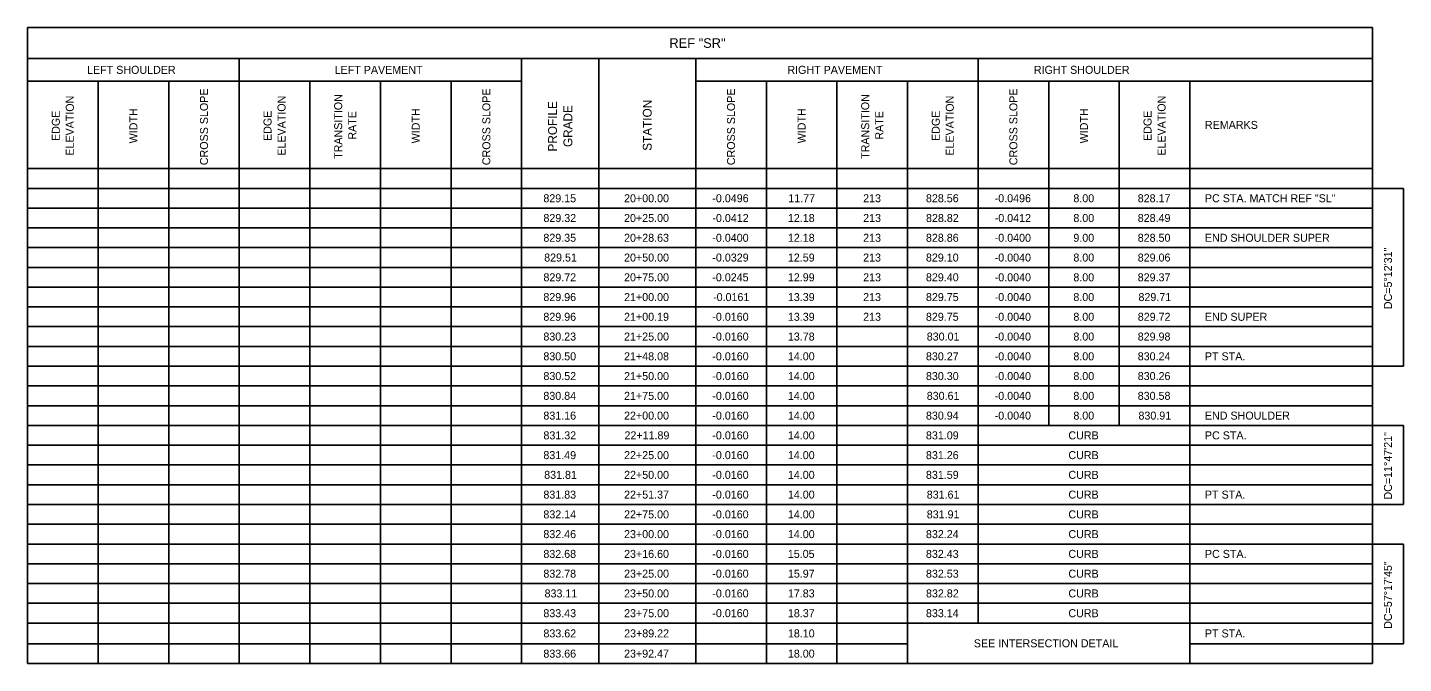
# Model space of a CAD drawing. Extents: x -31.2 to 34, y 0 to 30.3.
# Drawn here: x -31.16 to -7.08, y 4.37 to 15.51 of the extents above; entities that cross this region are included whole.
import ezdxf

# ---------------------------------------------------------------- set-up
doc = ezdxf.new("R2010")
doc.units = 0
doc.layers.add('Default', color=7, linetype='Continuous')

msp = doc.modelspace()

# ---------------------------------------------------------------- linework, layer by layer
at = {"layer": 'Default'}
for p, q in [((-31.159, 15.508), (-7.624, 15.508)), ((-31.159, 15.508), (-31.159, 4.374)), ((-7.624, 15.508), (-7.624, 4.374)), ((-31.159, 14.965), (-7.624, 14.965)), ((-27.454, 14.965), (-27.454, 4.374)), ((-22.513, 14.965), (-22.513, 4.374)), ((-21.162, 14.965), (-21.162, 4.374)), ((-19.466, 14.965), (-19.466, 4.374)), ((-14.525, 14.965), (-14.525, 5.083)), ((-31.159, 14.569), (-22.513, 14.569)), ((-29.924, 14.569), (-29.924, 13.038)), ((-28.689, 14.569), (-28.689, 13.038)), ((-26.218, 14.569), (-26.218, 4.374)), ((-24.983, 14.569), (-24.983, 4.374)), ((-23.748, 14.569), (-23.748, 4.374)), ((-19.466, 14.569), (-7.624, 14.569)), ((-18.23, 14.569), (-18.23, 4.374)), ((-16.995, 14.569), (-16.995, 4.374)), ((-15.76, 14.569), (-15.76, 4.374)), ((-13.289, 14.569), (-13.289, 13.038)), ((-12.054, 14.569), (-12.054, 13.038)), ((-10.819, 14.569), (-10.819, 4.374)), ((-31.159, 13.038), (-7.624, 13.038)), ((-29.924, 13.038), (-29.924, 4.374)), ((-28.689, 13.038), (-28.689, 4.374)), ((-13.289, 13.038), (-13.289, 8.541)), ((-12.054, 13.038), (-12.054, 8.541)), ((-31.159, 12.692), (-7.624, 12.692)), ((-7.624, 12.692), (-7.08, 12.692)), ((-7.08, 12.692), (-7.08, 9.579)), ((-31.159, 12.346), (-7.624, 12.346)), ((-31.159, 12), (-7.624, 12)), ((-31.159, 11.654), (-7.624, 11.654)), ((-31.159, 11.308), (-7.624, 11.308)), ((-31.159, 10.962), (-7.624, 10.962)), ((-31.159, 10.616), (-7.624, 10.616)), ((-31.159, 10.271), (-7.624, 10.271)), ((-31.159, 9.925), (-7.624, 9.925)), ((-31.159, 9.579), (-7.624, 9.579)), ((-7.624, 9.579), (-7.08, 9.579)), ((-31.159, 9.233), (-7.624, 9.233)), ((-31.159, 8.887), (-7.624, 8.887)), ((-31.159, 8.541), (-7.624, 8.541)), ((-7.624, 8.541), (-7.08, 8.541)), ((-7.08, 8.541), (-7.08, 7.158)), ((-31.159, 8.195), (-7.624, 8.195)), ((-31.159, 7.85), (-7.624, 7.85)), ((-31.159, 7.504), (-7.624, 7.504)), ((-31.159, 7.158), (-7.624, 7.158)), ((-7.624, 7.158), (-7.08, 7.158)), ((-31.159, 6.812), (-7.624, 6.812)), ((-31.159, 6.466), (-7.624, 6.466)), ((-7.624, 6.466), (-7.08, 6.466)), ((-7.08, 6.466), (-7.08, 4.72)), ((-31.159, 6.12), (-7.624, 6.12)), ((-31.159, 5.774), (-7.624, 5.774)), ((-31.159, 5.428), (-7.624, 5.428)), ((-31.159, 5.083), (-7.624, 5.083)), ((-31.159, 4.72), (-15.76, 4.72)), ((-10.819, 4.72), (-7.624, 4.72)), ((-7.624, 4.72), (-7.08, 4.72)), ((-31.159, 4.374), (-7.624, 4.374))]:
    msp.add_line(p, q, dxfattribs=at)

# ---------------------------------------------------------------- texts
for s, height, p in [('REF "SR"', 0.168, (-19.927, 15.152)), ('LEFT SHOULDER', 0.14, (-30.117, 14.697)), ('LEFT PAVEMENT', 0.14, (-25.785, 14.697)), ('RIGHT PAVEMENT', 0.14, (-17.862, 14.697)), ('RIGHT SHOULDER', 0.14, (-13.548, 14.697)), ('REMARKS', 0.14, (-10.555, 13.733)), ('829.15', 0.14, (-22.132, 12.449)), ('20+00.00', 0.14, (-20.72, 12.449)), ('-0.0496', 0.14, (-19.175, 12.449)), ('11.77', 0.14, (-17.846, 12.449)), ('213', 0.14, (-16.536, 12.449)), ('828.56', 0.14, (-15.437, 12.449)), ('-0.0496', 0.14, (-14.234, 12.449)), ('8.00', 0.14, (-12.857, 12.449)), ('828.17', 0.14, (-11.731, 12.449)), ('PC STA. MATCH REF "SL"', 0.14, (-10.555, 12.449)), ('829.32', 0.14, (-22.131, 12.103)), ('20+25.00', 0.14, (-20.72, 12.103)), ('-0.0412', 0.14, (-19.174, 12.103)), ('12.18', 0.14, (-17.853, 12.103)), ('213', 0.14, (-16.536, 12.103)), ('828.82', 0.14, (-15.436, 12.103)), ('-0.0412', 0.14, (-14.233, 12.103)), ('8.00', 0.14, (-12.857, 12.103)), ('828.49', 0.14, (-11.731, 12.103)), ('829.35', 0.14, (-22.132, 11.757)), ('20+28.63', 0.14, (-20.72, 11.757)), ('-0.0400', 0.14, (-19.175, 11.757)), ('12.18', 0.14, (-17.853, 11.757)), ('213', 0.14, (-16.536, 11.757)), ('828.86', 0.14, (-15.437, 11.757)), ('-0.0400', 0.14, (-14.234, 11.757)), ('9.00', 0.14, (-12.857, 11.757)), ('828.50', 0.14, (-11.731, 11.757)), ('END SHOULDER SUPER', 0.14, (-10.555, 11.757)), ('829.51', 0.14, (-22.118, 11.411)), ('20+50.00', 0.14, (-20.72, 11.411)), ('-0.0329', 0.14, (-19.175, 11.411)), ('12.59', 0.14, (-17.853, 11.411)), ('213', 0.14, (-16.536, 11.411)), ('829.10', 0.14, (-15.437, 11.411)), ('-0.0040', 0.14, (-14.234, 11.411)), ('8.00', 0.14, (-12.857, 11.411)), ('829.06', 0.14, (-11.731, 11.411)), ('829.72', 0.14, (-22.131, 11.065)), ('20+75.00', 0.14, (-20.72, 11.065)), ('-0.0245', 0.14, (-19.176, 11.065)), ('12.99', 0.14, (-17.853, 11.065)), ('213', 0.14, (-16.536, 11.065)), ('829.40', 0.14, (-15.437, 11.065)), ('-0.0040', 0.14, (-14.234, 11.065)), ('8.00', 0.14, (-12.857, 11.065)), ('829.37', 0.14, (-11.731, 11.065)), ('829.96', 0.14, (-22.132, 10.719)), ('21+00.00', 0.14, (-20.72, 10.719)), ('-0.0161', 0.14, (-19.162, 10.719)), ('13.39', 0.14, (-17.853, 10.719)), ('213', 0.14, (-16.536, 10.719)), ('829.75', 0.14, (-15.437, 10.719)), ('-0.0040', 0.14, (-14.234, 10.719)), ('8.00', 0.14, (-12.857, 10.719)), ('829.71', 0.14, (-11.718, 10.719)), ('829.96', 0.14, (-22.132, 10.374)), ('21+00.19', 0.14, (-20.72, 10.374)), ('-0.0160', 0.14, (-19.175, 10.374)), ('13.39', 0.14, (-17.853, 10.374)), ('213', 0.14, (-16.536, 10.374)), ('829.75', 0.14, (-15.437, 10.374)), ('-0.0040', 0.14, (-14.234, 10.374)), ('8.00', 0.14, (-12.857, 10.374)), ('829.72', 0.14, (-11.73, 10.374)), ('END SUPER', 0.14, (-10.555, 10.374)), ('830.23', 0.14, (-22.132, 10.028)), ('21+25.00', 0.14, (-20.72, 10.028)), ('-0.0160', 0.14, (-19.175, 10.028)), ('13.78', 0.14, (-17.853, 10.028)), ('830.01', 0.14, (-15.423, 10.028)), ('-0.0040', 0.14, (-14.234, 10.028)), ('8.00', 0.14, (-12.857, 10.028)), ('829.98', 0.14, (-11.731, 10.028)), ('830.50', 0.14, (-22.132, 9.682)), ('21+48.08', 0.14, (-20.72, 9.682)), ('-0.0160', 0.14, (-19.175, 9.682)), ('14.00', 0.14, (-17.853, 9.682)), ('830.27', 0.14, (-15.437, 9.682)), ('-0.0040', 0.14, (-14.234, 9.682)), ('8.00', 0.14, (-12.857, 9.682)), ('830.24', 0.14, (-11.731, 9.682)), ('PT STA.', 0.14, (-10.555, 9.682)), ('830.52', 0.14, (-22.131, 9.336)), ('21+50.00', 0.14, (-20.72, 9.336)), ('-0.0160', 0.14, (-19.175, 9.336)), ('14.00', 0.14, (-17.853, 9.336)), ('830.30', 0.14, (-15.437, 9.336)), ('-0.0040', 0.14, (-14.234, 9.336)), ('8.00', 0.14, (-12.857, 9.336)), ('830.26', 0.14, (-11.731, 9.336)), ('830.84', 0.14, (-22.132, 8.99)), ('21+75.00', 0.14, (-20.72, 8.99)), ('-0.0160', 0.14, (-19.175, 8.99)), ('14.00', 0.14, (-17.853, 8.99)), ('830.61', 0.14, (-15.423, 8.99)), ('-0.0040', 0.14, (-14.234, 8.99)), ('8.00', 0.14, (-12.857, 8.99)), ('830.58', 0.14, (-11.731, 8.99)), ('831.16', 0.14, (-22.132, 8.644)), ('22+00.00', 0.14, (-20.72, 8.644)), ('-0.0160', 0.14, (-19.175, 8.644)), ('14.00', 0.14, (-17.853, 8.644)), ('830.94', 0.14, (-15.437, 8.644)), ('-0.0040', 0.14, (-14.234, 8.644)), ('8.00', 0.14, (-12.857, 8.644)), ('830.91', 0.14, (-11.718, 8.644)), ('END SHOULDER', 0.14, (-10.555, 8.644)), ('831.32', 0.14, (-22.131, 8.298)), ('22+11.89', 0.14, (-20.713, 8.298)), ('-0.0160', 0.14, (-19.175, 8.298)), ('14.00', 0.14, (-17.853, 8.298)), ('831.09', 0.14, (-15.437, 8.298)), ('CURB', 0.14, (-12.944, 8.298)), ('PC STA.', 0.14, (-10.555, 8.298)), ('831.49', 0.14, (-22.132, 7.952)), ('22+25.00', 0.14, (-20.72, 7.952)), ('-0.0160', 0.14, (-19.175, 7.952)), ('14.00', 0.14, (-17.853, 7.952)), ('831.26', 0.14, (-15.437, 7.952)), ('CURB', 0.14, (-12.944, 7.952)), ('831.81', 0.14, (-22.118, 7.607)), ('22+50.00', 0.14, (-20.72, 7.607)), ('-0.0160', 0.14, (-19.175, 7.607)), ('14.00', 0.14, (-17.853, 7.607)), ('831.59', 0.14, (-15.437, 7.607)), ('CURB', 0.14, (-12.944, 7.607)), ('831.83', 0.14, (-22.132, 7.261)), ('22+51.37', 0.14, (-20.72, 7.261)), ('-0.0160', 0.14, (-19.175, 7.261)), ('14.00', 0.14, (-17.853, 7.261)), ('831.61', 0.14, (-15.423, 7.261)), ('CURB', 0.14, (-12.944, 7.261)), ('PT STA.', 0.14, (-10.555, 7.261)), ('832.14', 0.14, (-22.132, 6.915)), ('22+75.00', 0.14, (-20.72, 6.915)), ('-0.0160', 0.14, (-19.175, 6.915)), ('14.00', 0.14, (-17.853, 6.915)), ('831.91', 0.14, (-15.423, 6.915)), ('CURB', 0.14, (-12.944, 6.915)), ('832.46', 0.14, (-22.132, 6.569)), ('23+00.00', 0.14, (-20.72, 6.569)), ('-0.0160', 0.14, (-19.175, 6.569)), ('14.00', 0.14, (-17.853, 6.569)), ('832.24', 0.14, (-15.437, 6.569)), ('CURB', 0.14, (-12.944, 6.569)), ('832.68', 0.14, (-22.132, 6.223)), ('23+16.60', 0.14, (-20.72, 6.223)), ('-0.0160', 0.14, (-19.175, 6.223)), ('15.05', 0.14, (-17.854, 6.223)), ('832.43', 0.14, (-15.437, 6.223)), ('CURB', 0.14, (-12.944, 6.223)), ('PC STA.', 0.14, (-10.555, 6.223)), ('832.78', 0.14, (-22.132, 5.877)), ('23+25.00', 0.14, (-20.72, 5.877)), ('-0.0160', 0.14, (-19.175, 5.877)), ('15.97', 0.14, (-17.853, 5.877)), ('832.53', 0.14, (-15.437, 5.877)), ('CURB', 0.14, (-12.944, 5.877)), ('833.11', 0.14, (-22.111, 5.531)), ('23+50.00', 0.14, (-20.72, 5.531)), ('-0.0160', 0.14, (-19.175, 5.531)), ('17.83', 0.14, (-17.853, 5.531)), ('832.82', 0.14, (-15.436, 5.531)), ('CURB', 0.14, (-12.944, 5.531)), ('833.43', 0.14, (-22.132, 5.185)), ('23+75.00', 0.14, (-20.72, 5.185)), ('-0.0160', 0.14, (-19.175, 5.185)), ('18.37', 0.14, (-17.853, 5.185)), ('833.14', 0.14, (-15.437, 5.185)), ('CURB', 0.14, (-12.944, 5.185)), ('833.62', 0.14, (-22.131, 4.831)), ('23+89.22', 0.14, (-20.719, 4.831)), ('18.10', 0.14, (-17.853, 4.831)), ('PT STA.', 0.14, (-10.555, 4.831)), ('833.66', 0.14, (-22.132, 4.477)), ('23+92.47', 0.14, (-20.72, 4.477)), ('18.00', 0.14, (-17.853, 4.477)), ('SEE INTERSECTION DETAIL', 0.14, (-14.599, 4.658))]:
    msp.add_text(s, height=height, dxfattribs=at).set_placement(p)
for s, height, p in [('ELEVATION', 0.14, (-30.349, 13.264)), ('CROSS SLOPE', 0.14, (-28.001, 13.098)), ('ELEVATION', 0.14, (-26.644, 13.264)), ('TRANSITION ', 0.14, (-25.653, 13.208)), ('CROSS SLOPE', 0.14, (-23.06, 13.098)), ('PROFILE ', 0.154, (-21.895, 13.338)), ('STATION', 0.154, (-20.237, 13.35)), ('CROSS SLOPE', 0.14, (-18.778, 13.098)), ('TRANSITION ', 0.14, (-16.43, 13.208)), ('ELEVATION', 0.14, (-14.95, 13.264)), ('CROSS SLOPE', 0.14, (-13.837, 13.098)), ('ELEVATION', 0.14, (-11.244, 13.264)), ('EDGE ', 0.14, (-30.594, 13.522)), ('WIDTH', 0.14, (-29.237, 13.48)), ('EDGE ', 0.14, (-26.889, 13.522)), ('RATE', 0.14, (-25.408, 13.545)), ('WIDTH', 0.14, (-24.296, 13.48)), ('GRADE', 0.154, (-21.626, 13.416)), ('WIDTH', 0.14, (-17.543, 13.48)), ('RATE', 0.14, (-16.185, 13.545)), ('EDGE ', 0.14, (-15.195, 13.522)), ('WIDTH', 0.14, (-12.602, 13.48)), ('EDGE ', 0.14, (-11.489, 13.522)), ('DC=5°12\'31"', 0.14, (-7.282, 10.577)), ('DC=11°47\'21"', 0.14, (-7.282, 7.244)), ('DC=57°17\'45"', 0.14, (-7.282, 4.981))]:
    msp.add_text(s, height=height, rotation=90, dxfattribs=at).set_placement(p)

doc.saveas('drawing.dxf')
